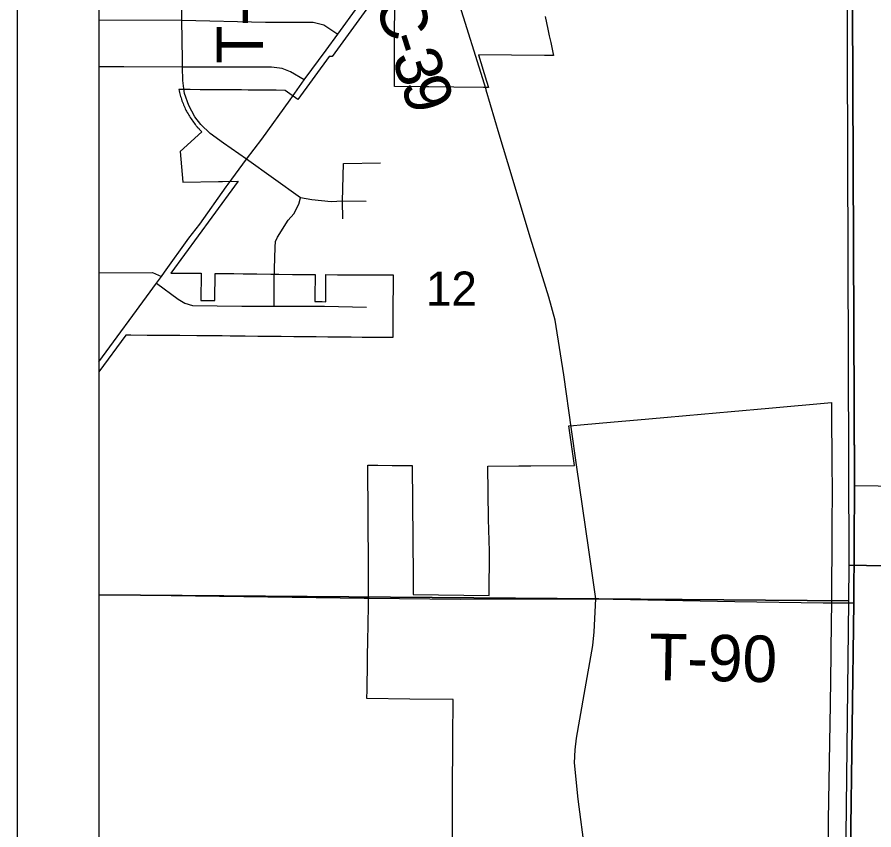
# Model space of a CAD drawing. Extents: x 0 to 34, y 0 to 22.
# Drawn here: x 2 to 3.047, y 15.156 to 16.149 of the extents above; entities that cross this region are included whole.
import ezdxf

# ---------------------------------------------------------------- set-up
doc = ezdxf.new("R2010")
doc.units = 0
for name, color, linetype in [('Default', 7, 'Continuous'), ('GM_X_City_Street', 7, 'Continuous'), ('GM_X_County_Road', 7, 'Continuous'), ('GM_X_County_Road_Text', 7, 'Continuous'), ('GM_X_Section', 7, 'Continuous'), ('GM_X_Section_Text', 7, 'Continuous'), ('GM_X_State_Route', 7, 'Continuous'), ('GM_X_Township_Road', 7, 'Continuous'), ('GM_X_Township_Road_Text', 7, 'Continuous'), ('SH_Data', 7, 'Continuous')]:
    doc.layers.add(name, color=color, linetype=linetype)

msp = doc.modelspace()

# ---------------------------------------------------------------- linework, layer by layer
at = {"layer": 'Default'}
for points in [[(2.1, 16.4848), (2.1, 15.4427), (3.0163, 15.4353), (3.0168, 15.4789), (3.0135, 16.4807)], [(2.1, 15.4427), (2.1, 14.4681), (3.0051, 14.4664), (3.0163, 15.4353)]]:
    msp.add_lwpolyline(points, close=True, dxfattribs=at)
at = {"layer": 'GM_X_City_Street'}
for points in [[(2.4263, 15.9235), (2.3976, 15.9239), (2.3835, 15.9232), (2.3717, 15.9242), (2.3602, 15.9255), (2.3461, 15.9282), (2.2804, 15.9752)], [(2.398, 15.9026), (2.3976, 15.9239), (2.3986, 15.97), (2.4438, 15.9707)], [(2.3141, 15.8282), (2.3151, 15.8676), (2.3158, 15.8747), (2.3181, 15.8801), (2.3312, 15.9006), (2.338, 15.9087), (2.3441, 15.9205), (2.3461, 15.9282)], [(3.0236, 15.5763), (3.3371, 15.5721)]]:
    msp.add_lwpolyline(points, dxfattribs=at)
at = {"layer": 'GM_X_County_Road'}
for points in [[(3.0235, 15.5833), (3.02, 16.3581), (3.0182, 16.4158)], [(2.5732, 16.0595), (2.5729, 16.0605), (2.5369, 16.1764), (2.5102, 16.27)], [(2.6773, 15.6449), (2.668, 15.7119), (2.6639, 15.7373), (2.6574, 15.7784), (2.6496, 15.8066), (2.6274, 15.8786), (2.5997, 15.9709), (2.5891, 16.006), (2.5732, 16.0595)], [(2.7071, 15.4379), (2.6985, 15.4977), (2.6833, 15.6016), (2.6773, 15.6449)], [(3.0165, 14.9818), (3.0224, 15.4329), (3.0236, 15.5763), (3.0235, 15.5833)], [(2.6941, 15.1277), (2.6856, 15.193), (2.6812, 15.2376), (2.6817, 15.2532), (2.6833, 15.2676), (2.693, 15.3211), (2.7034, 15.3811), (2.705, 15.3975), (2.7071, 15.4379)]]:
    msp.add_lwpolyline(points, dxfattribs=at)
at = {"layer": 'GM_X_Section'}
for points in [[(3.0135, 16.4807), (4.0113, 16.4768), (4.0112, 15.46), (3.0168, 15.4789)], [(3.0168, 15.4789), (4.0112, 15.46), (4.0068, 14.8003), (3.9922, 14.7706), (3.9618, 14.7034), (3.9313, 14.6142), (3.9035, 14.5261), (3.8947, 14.4604), (3.0051, 14.4664), (3.0163, 15.4353)]]:
    msp.add_lwpolyline(points, close=True, dxfattribs=at)
at = {"layer": 'GM_X_State_Route'}
for points in [[(2.3334, 16.0479), (2.3508, 16.0723), (2.3775, 16.1087), (2.3919, 16.1283), (2.4166, 16.1625), (2.4419, 16.1972), (2.4592, 16.2187), (2.4869, 16.2465), (2.5102, 16.27)], [(2.4523, 16.1939), (2.4043, 16.1276), (2.385, 16.101), (2.3812, 16.1009), (2.343, 16.0482), (2.3274, 16.0594), (2.3166, 16.0596), (2.3105, 16.0596), (2.3024, 16.0597), (2.2882, 16.0598), (2.2821, 16.0598), (2.274, 16.0599), (2.2668, 16.0599), (2.2631, 16.0599), (2.2602, 16.06), (2.2557, 16.06), (2.2486, 16.06), (2.2354, 16.0601), (2.2238, 16.0602), (2.2113, 16.0603), (2.1977, 16.0604), (2.198, 16.0587), (2.1984, 16.057), (2.1989, 16.0552), (2.1993, 16.0535), (2.1998, 16.0518), (2.2003, 16.0501), (2.2009, 16.0485), (2.2014, 16.0468), (2.2021, 16.0451), (2.2027, 16.0435), (2.2034, 16.0418), (2.204, 16.0402), (2.2048, 16.0386), (2.2055, 16.037), (2.2063, 16.0354), (2.2071, 16.0338), (2.2072, 16.0336), (2.2079, 16.0323), (2.2088, 16.0307), (2.2097, 16.0292), (2.2106, 16.0277), (2.2115, 16.0262), (2.2125, 16.0247), (2.2135, 16.0232), (2.2145, 16.0218), (2.2155, 16.0204), (2.2166, 16.019), (2.2177, 16.0176), (2.2182, 16.017), (2.2188, 16.0162), (2.22, 16.0148), (2.2201, 16.0146), (2.2211, 16.0135), (2.2223, 16.0122), (2.2225, 16.012), (2.2235, 16.0109), (2.2249, 16.0094), (2.2258, 16.0086), (2.1993, 15.9847), (2.2024, 15.9471), (2.2461, 15.9479), (2.2509, 15.948), (2.2699, 15.9483), (2.238, 15.9046), (2.1879, 15.8361), (2.1926, 15.8361), (2.2166, 15.8358), (2.2248, 15.8358), (2.2245, 15.8026), (2.2322, 15.8025), (2.2416, 15.8025), (2.2416, 15.8034), (2.2419, 15.8356), (2.2589, 15.8354), (2.2648, 15.8354), (2.276, 15.8353), (2.293, 15.8351), (2.3101, 15.8348), (2.3196, 15.8346), (2.3366, 15.8345), (2.3499, 15.8344), (2.3641, 15.8343), (2.3638, 15.8067), (2.3637, 15.8012), (2.3727, 15.8012), (2.377, 15.8011), (2.3773, 15.8342), (2.3915, 15.8341), (2.3991, 15.834), (2.4048, 15.834), (2.42, 15.8339), (2.4507, 15.8338), (2.4596, 15.8338), (2.4593, 15.8198), (2.4592, 15.7982), (2.4592, 15.7824), (2.4591, 15.7747), (2.4591, 15.7724), (2.4591, 15.7716), (2.4591, 15.7575), (2.4214, 15.7575), (2.408, 15.7577), (2.3938, 15.7578), (2.3796, 15.7579), (2.3654, 15.7581), (2.3521, 15.7582), (2.3379, 15.7583), (2.3228, 15.7585), (2.3143, 15.7586), (2.3081, 15.7586), (2.2939, 15.7587), (2.2788, 15.7589), (2.2646, 15.759), (2.2603, 15.7591), (2.2504, 15.7592), (2.2362, 15.7593), (2.232, 15.7593), (2.2279, 15.7594), (2.2196, 15.7595), (2.1986, 15.7596), (2.1676, 15.7599), (2.1587, 15.76), (2.1391, 15.7602), (2.1373, 15.7603), (2.1327, 15.7603), (2.1, 15.7155), (2.1, 14.4056)], [(2.6452, 16.1499), (2.6486, 16.1341), (2.6502, 16.1262), (2.652, 16.1181), (2.6547, 16.1055), (2.6554, 16.1019), (2.6443, 16.102), (2.5638, 16.1028), (2.5736, 16.0708), (2.576, 16.0629), (2.57, 16.0629), (2.5337, 16.0633), (2.5032, 16.0636), (2.4929, 16.0637), (2.461, 16.064), (2.4611, 16.0877), (2.4611, 16.102), (2.4611, 16.1033), (2.4611, 16.1066), (2.4612, 16.1256), (2.4614, 16.1634)], [(2.2804, 15.9752), (2.2991, 15.9999), (2.3334, 16.0479)], [(2.2556, 15.9416), (2.258, 15.9449), (2.2804, 15.9752)], [(2.1702, 15.8238), (2.1762, 15.832), (2.18, 15.8371), (2.2098, 15.8787), (2.2231, 15.8958), (2.2556, 15.9416)], [(2.1, 15.7277), (2.1222, 15.7581), (2.1414, 15.7841), (2.1702, 15.8238)], [(2.532, 15.1386), (2.5319, 15.1867), (2.5319, 15.2173), (2.5322, 15.2494), (2.5324, 15.2684), (2.5325, 15.2804), (2.5327, 15.3021), (2.5329, 15.3147), (2.48, 15.3155), (2.4273, 15.3162), (2.4275, 15.3267), (2.4286, 15.3944), (2.4287, 15.3985), (2.4293, 15.4382), (2.4293, 15.4439), (2.4293, 15.4461), (2.4293, 15.4478), (2.4292, 15.4754), (2.4286, 15.6015), (2.4408, 15.6014), (2.4584, 15.6011), (2.4825, 15.6008), (2.4837, 15.4652), (2.4839, 15.4432), (2.5768, 15.4422), (2.577, 15.4962), (2.5759, 15.5355), (2.5753, 15.5999), (2.613, 15.6004), (2.6278, 15.6005), (2.6811, 15.6011), (2.6741, 15.6493), (2.6797, 15.6498), (2.6885, 15.6506), (2.7293, 15.6542), (2.7579, 15.6568), (2.7903, 15.6597), (2.8173, 15.662), (2.8723, 15.6669), (2.9185, 15.671), (2.9949, 15.6778), (2.9949, 15.6759), (2.9956, 15.5932), (2.9957, 15.5802), (2.9957, 15.5781), (2.9957, 15.5757), (2.9954, 15.5228), (2.9954, 15.5154), (2.995, 15.4391), (2.995, 15.4315), (2.9947, 15.4097), (2.9946, 15.4022), (2.9943, 15.3807), (2.9941, 15.3701), (2.9932, 15.3087), (2.9925, 15.2623), (2.9911, 15.1676), (2.9905, 15.1263)]]:
    msp.add_lwpolyline(points, dxfattribs=at)
at = {"layer": 'GM_X_Township_Road'}
for p, q in [((2.3141, 15.7956), (2.3141, 15.8282)), ((2.9928, 15.4332), (3.0224, 15.4329))]:
    msp.add_line(p, q, dxfattribs=at)
for points in [[(2.1, 17.494), (2.1, 14.1), (3.0031, 14.1), (3.0067, 14.4061), (3.0074, 14.465), (3.0123, 14.7921), (3.0162, 14.9764), (3.0222, 15.4334), (3.0233, 15.5768), (3.0198, 16.3586)], [(3.0198, 16.3586), (3.0233, 15.5768), (3.0222, 15.4334), (3.0162, 14.9764), (3.0123, 14.7921), (3.0074, 14.465), (3.0067, 14.4061), (3.0031, 14.1), (3.9251, 14.1)], [(2.2039, 16.0584), (2.2024, 16.0713), (2.202, 16.0877), (2.202, 16.0967), (2.2013, 16.1452), (2.2018, 16.1738), (2.2021, 16.202), (2.2019, 16.2238), (2.2019, 16.2544), (2.2023, 16.2649)], [(2.1, 16.1456), (2.2013, 16.1452), (2.3035, 16.1428), (2.3619, 16.1428), (2.3748, 16.1395), (2.3919, 16.1283)], [(2.3508, 16.0723), (2.3339, 16.0821), (2.324, 16.086), (2.3108, 16.0876), (2.2594, 16.0877), (2.202, 16.0877), (2.1303, 16.0883), (2.1, 16.0881)], [(2.2804, 15.9752), (2.252, 15.9949), (2.236, 16.0069), (2.2244, 16.0179), (2.2171, 16.0271), (2.2099, 16.0409), (2.2043, 16.0554), (2.2039, 16.0584)], [(2.1, 15.8366), (2.1655, 15.8368), (2.1762, 15.832)], [(2.1702, 15.8238), (2.1968, 15.8042), (2.2051, 15.7992), (2.2143, 15.7966), (2.2745, 15.7957), (2.3141, 15.7956), (2.3755, 15.7956), (2.4268, 15.7945)], [(2.1, 15.4433), (2.3653, 15.4394), (2.424, 15.4388), (2.43, 15.4387)], [(2.43, 15.4387), (2.5415, 15.4375), (2.7071, 15.4379)], [(2.7071, 15.4379), (2.877, 15.4347), (2.9849, 15.4332), (2.9928, 15.4332)]]:
    msp.add_lwpolyline(points, dxfattribs=at)
at = {"layer": 'SH_Data'}
for p, q in [((2, 21), (2, 14)), ((2.1, 20.9), (2.1, 14.1))]:
    msp.add_line(p, q, dxfattribs=at)

# ---------------------------------------------------------------- texts
at = {"layer": 'GM_X_County_Road_Text'}
for s, rotation, p in [('C', 286.7142, (2.4369, 16.1685)), ('-', 287.5308, (2.4506, 16.123)), ('3', 287.6488, (2.4576, 16.1006)), ('9', 287.6886, (2.4683, 16.0672))]:
    msp.add_text(s, height=0.0568, rotation=rotation, dxfattribs=at).set_placement(p)
at = {"layer": 'GM_X_Section_Text'}
msp.add_text('12', height=0.04186, rotation=0, dxfattribs=at).set_placement((2.4995, 15.7961))
at = {"layer": 'GM_X_Township_Road_Text'}
for s, rotation, p in [('T-91', 89.9973, (2.3006, 16.092)), ('T-90', 358.9383, (2.7719, 15.3388))]:
    msp.add_text(s, height=0.05682, rotation=rotation, dxfattribs=at).set_placement(p)

doc.saveas('drawing.dxf')
